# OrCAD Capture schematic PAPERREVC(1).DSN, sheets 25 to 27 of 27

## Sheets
25 PAGE1 (25): size B; title: SNAP,  ZDOK CONNECTOR; block FPGA13
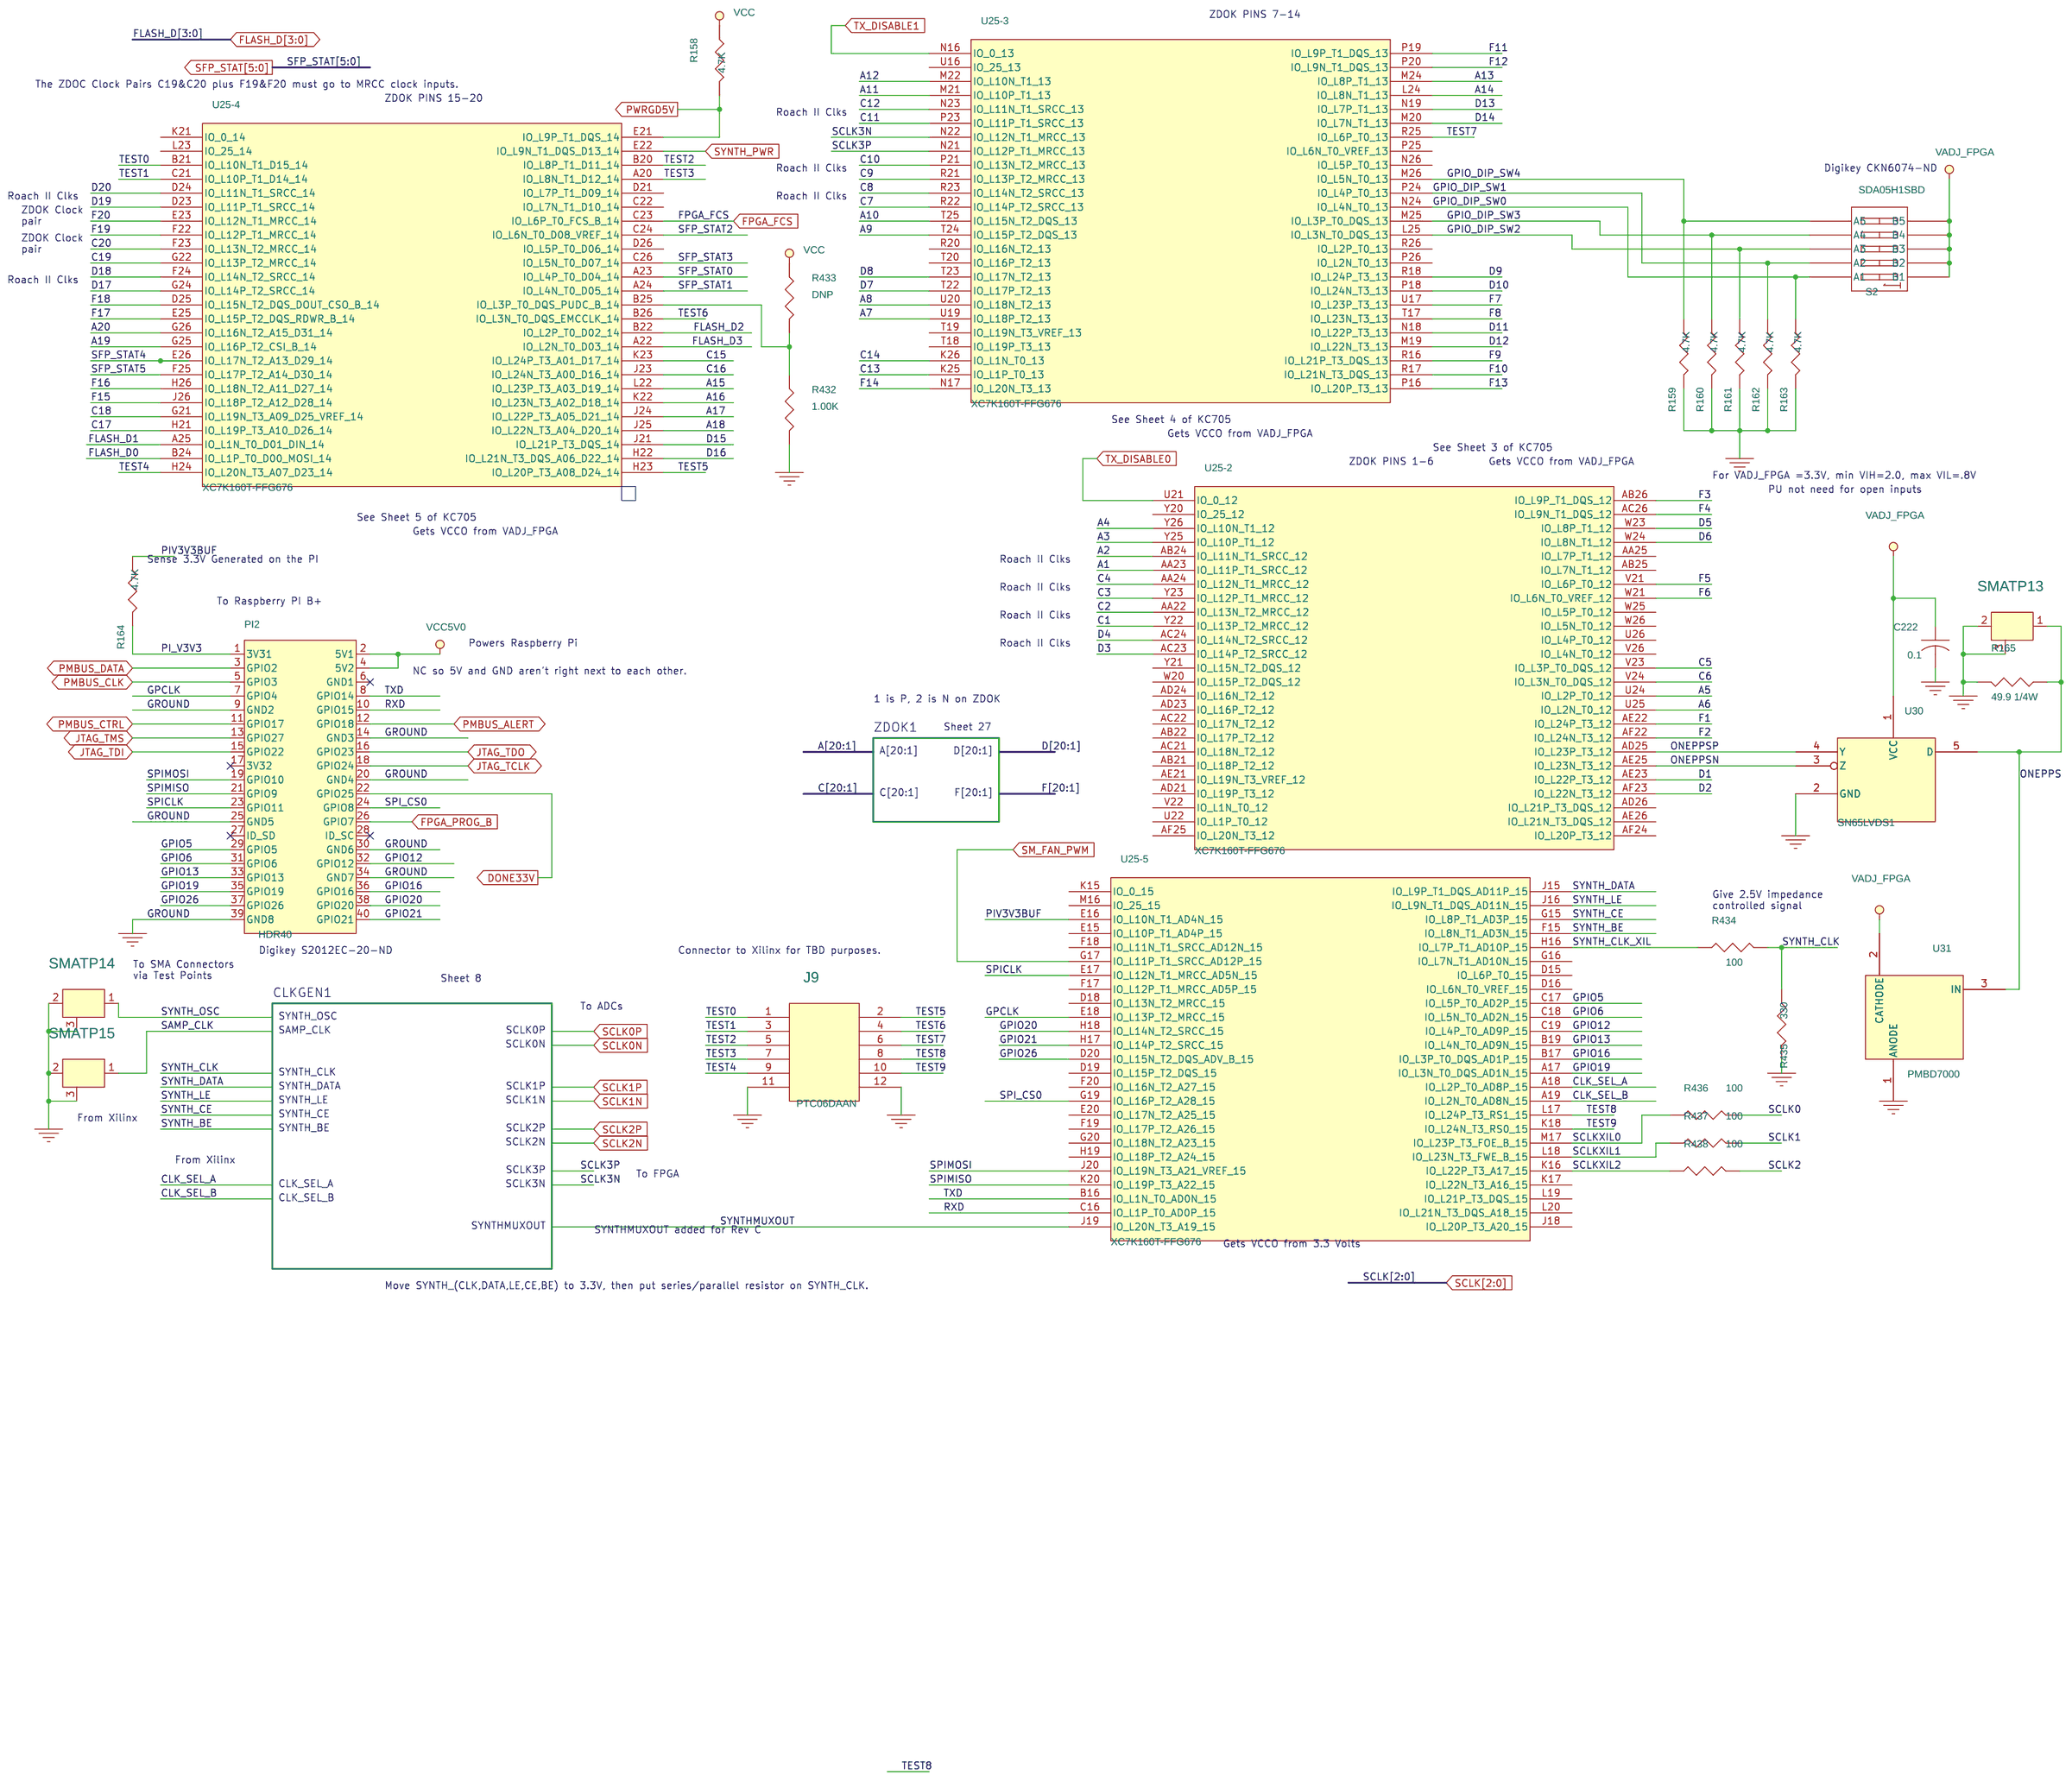
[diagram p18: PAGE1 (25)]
26 PAGE1 (26): size B; title: SNAP, Clock Generator; block FPGA13/CLKGEN1
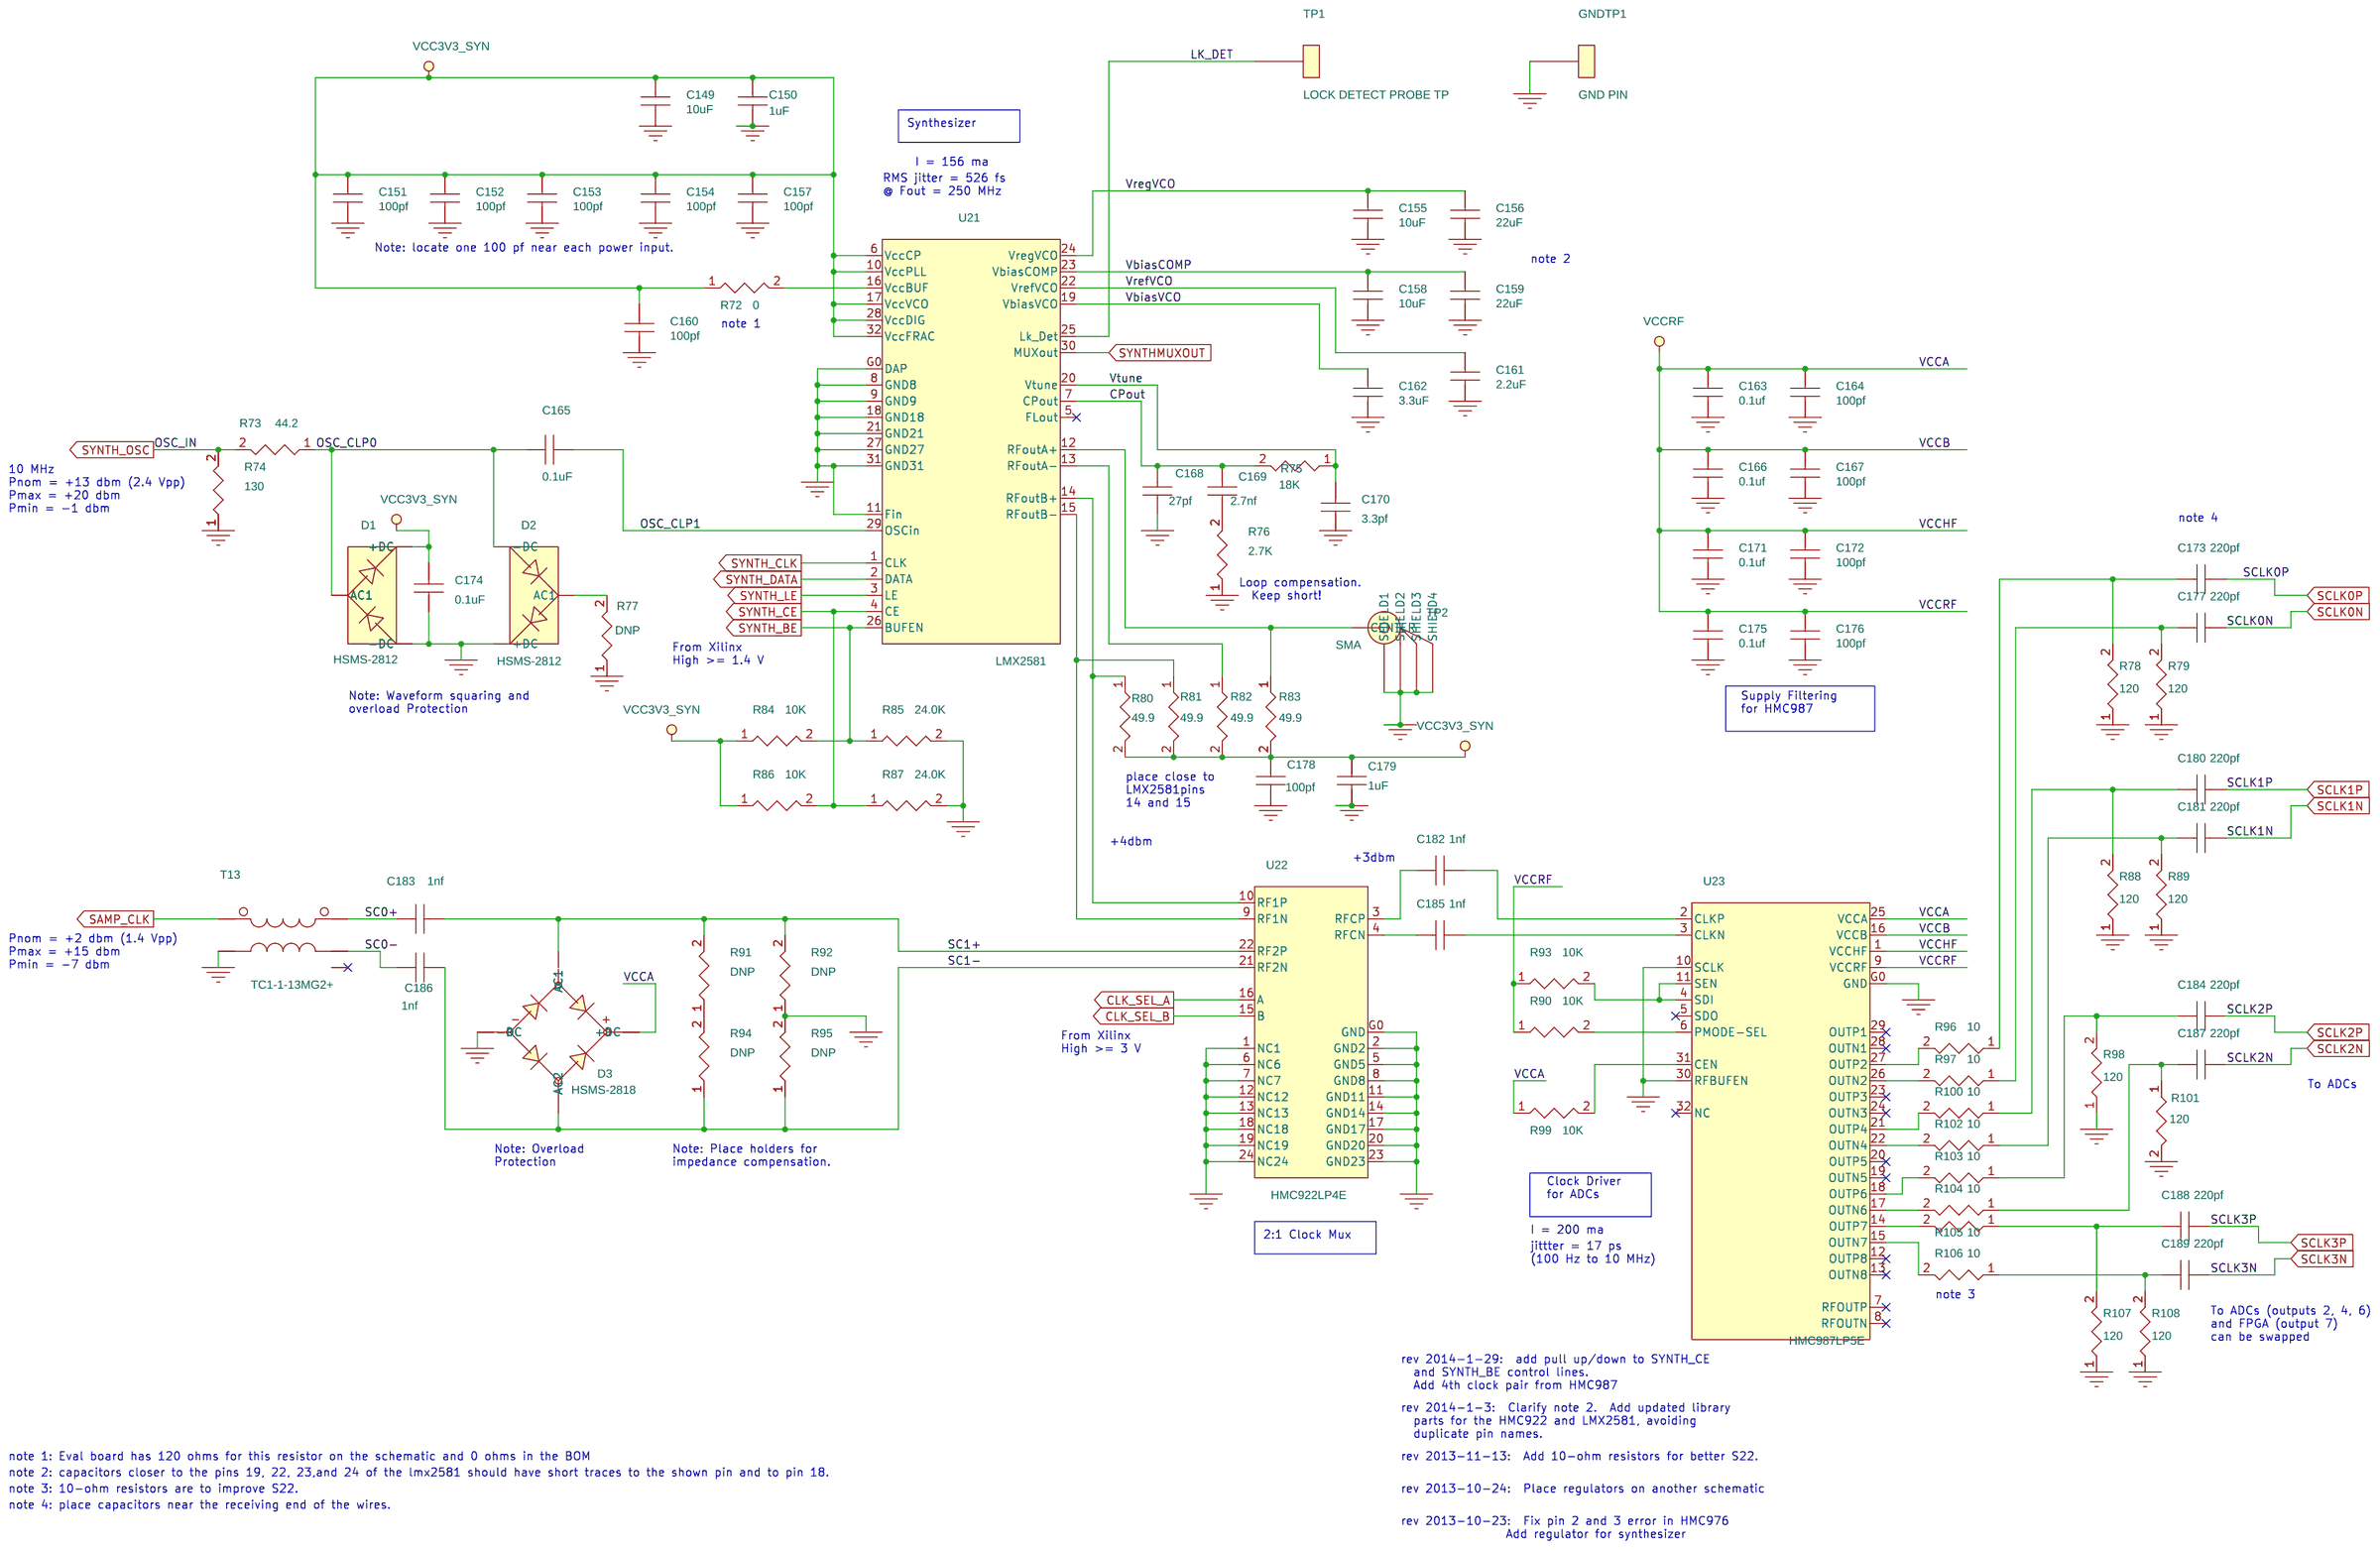
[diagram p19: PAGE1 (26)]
27 PAGE1 (27): size B; title: SNAP, ZDOK Connector; block FPGA13/ZDOK1
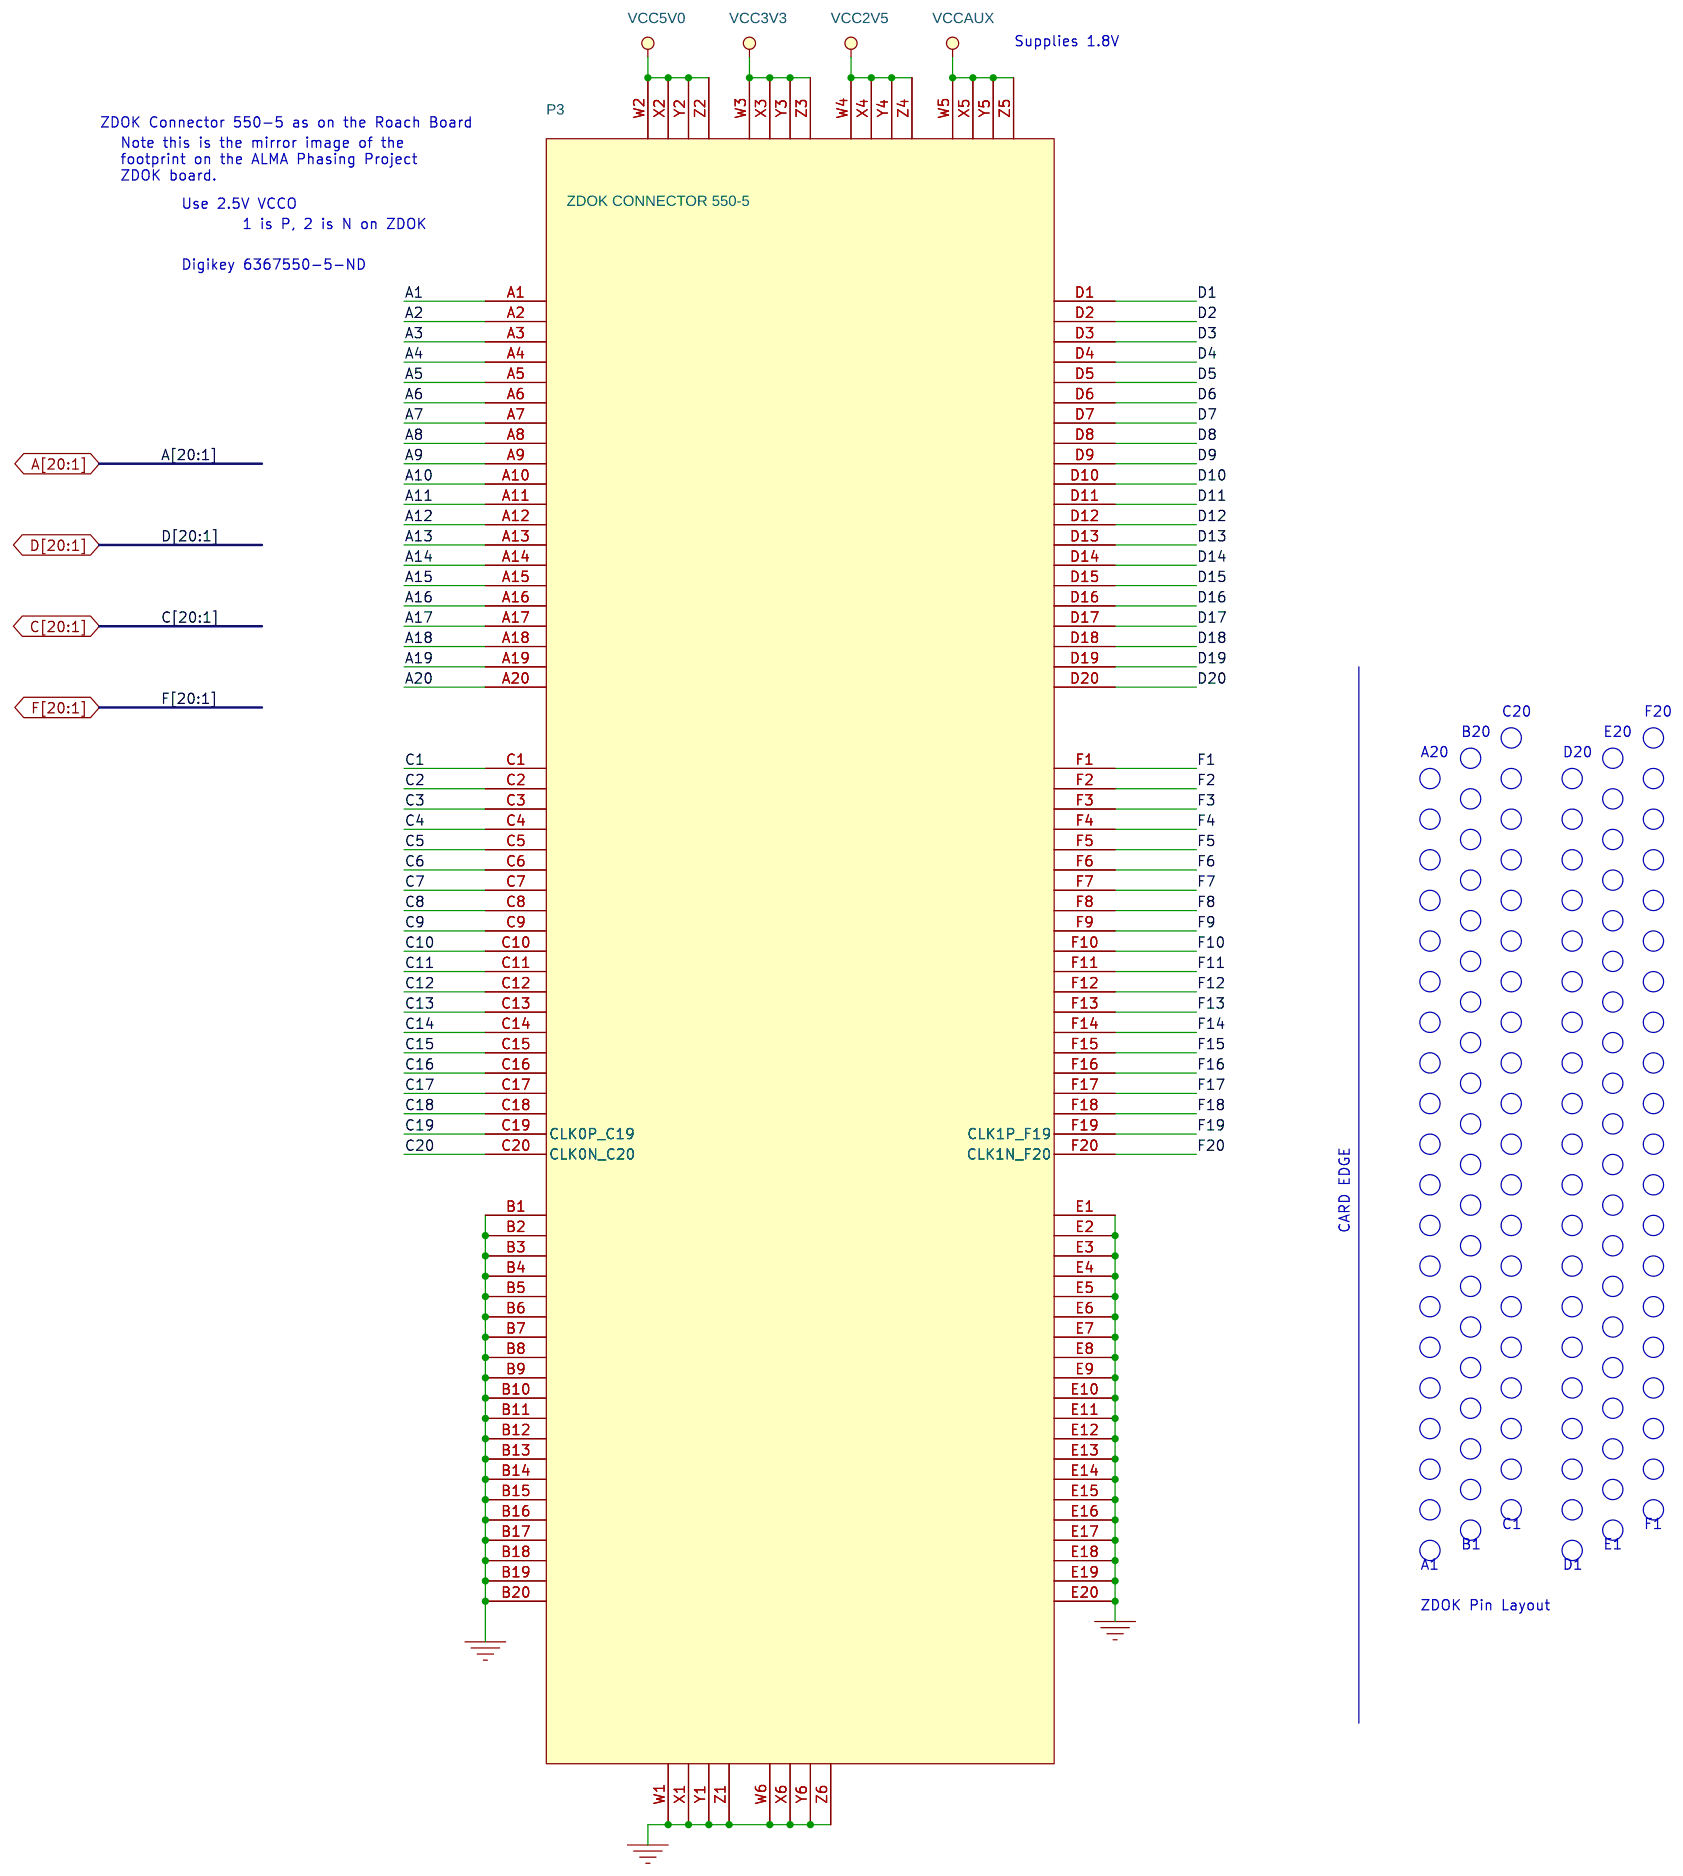
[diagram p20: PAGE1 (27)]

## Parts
sheet PAGE1 (3)
U25  XC7K160T-FFG676  [bga676c100p26x26_2700x2700x260]  (sections -1,-10,-11,-12,-13,-14,-2,-3,-4,-5,-6,-7,-8,-9)
sheet PAGE1 (25)
C222  0.1  [CAPC1005X50L]
J9  PTC06DAAN  [HDRV6X2]
PI2  HDR40  [HDRV2x20]
R158  4.7K  [RESC1005X35N]
R159  4.7K  [RESC1005X35N]
R160  4.7K  [RESC1005X35N]
R161  4.7K  [RESC1005X35N]
R162  4.7K  [RESC1005X35N]
R163  4.7K  [RESC1005X35N]
R164  4.7K  [RESC1005X35N]
R165  49.9 1/4W  [RESC3216X70N]
R432  1.00K  [RESC1005X35N]
R433  DNP  [RESC1005X35N]
R434  100  [RESC1005X35N]
R435  330  [RESC1608X50N]
R436  100  [RESC1005X35N]
R437  100  [RESC1005X35N]
R438  100  [RESC1005X35N]
S2  SDA05H1SBD  [SW_SDA05H1SBD]
SMATP13  SMATP  [SMA_END_LAUNCH]
SMATP14  SMATP  [SMA_END_LAUNCH]
SMATP15  SMATP  [SMA_END_LAUNCH]
U30  SN65LVDS1  [SOT95P280X145-5N]
U31  PMBD7000  [SOT95P240X110-3L16N]
sheet PAGE1 (26)
C149  10uF  [CAPC3216X180N]
C150  1uF  [CAPC1608X90N]
C151  100pf  [CAPC1005X50L]
C152  100pf  [CAPC1005X50L]
C153  100pf  [CAPC1005X50L]
C154  100pf  [CAPC1005X50L]
C155  10uF  [CAPC3216X180N]
C156  22uF  [CAPC3216X180N]
C157  100pf  [CAPC1005X50L]
C158  10uF  [CAPC3216X180N]
C159  22uF  [CAPC3216X180N]
C160  100pf  [CAPC1005X50L]
C161  2.2uF  [CAPC1608X90N]
C162  3.3uF  [CAPC2012X105N]
C163  0.1uf  [CAPC1005X50L]
C164  100pf  [CAPC1005X50L]
C165  0.1uF  [CAPC1005X50L]
C166  0.1uf  [CAPC1005X50L]
C167  100pf  [CAPC1005X50L]
C168  27pf  [CAPC1005X50L]
C169  2.7nf  [CAPC1608X90N]
C170  3.3pf  [CAPC1005X50N]
C171  0.1uf  [CAPC1005X50L]
C172  100pf  [CAPC1005X50L]
C173  220pf  [CAPC1005X50L]
C174  0.1uF  [CAPC1005X50L]
C175  0.1uf  [CAPC1005X50L]
C176  100pf  [CAPC1005X50L]
C177  220pf  [CAPC1005X50L]
C178  100pf  [CAPC1005X50L]
C179  1uF  [CAPC1608X90N]
C180  220pf  [CAPC1005X50L]
C181  220pf  [CAPC1005X50L]
C182  1nf  [CAPC1005X50L]
C183  1nf  [CAPC1005X50L]
C184  220pf  [CAPC1005X50L]
C185  1nf  [CAPC1005X50L]
C186  1nf  [CAPC1005X50L]
C187  220pf  [CAPC1005X50L]
C188  220pf  [CAPC1005X50L]
C189  220pf  [CAPC1005X50L]
D1  HSMS-2812  [SOT95P240X110-3L16N]
D2  HSMS-2812  [SOT95P240X110-3L16N]
D3  HSMS-2818  [SOT192P237X112-4L20N]
GNDTP1  GND PIN  [TP107]
R72  0  [RESC1005X35N]
R73  44.2  [RESC1005X35N]
R74  130  [RESC3216X70N]
R75  18K  [RESC1005X35N]
R76  2.7K  [RESC1005X35N]
R77  DNP  [RESC1005X35N]
R78  120  [RESC1608X50N]
R79  120  [RESC1608X50N]
R80  49.9  [RESC1005X35N]
R81  49.9  [RESC1005X35N]
R82  49.9  [RESC1005X35N]
R83  49.9  [RESC1005X35N]
R84  10K  [RESC1005X35N]
R85  24.0K  [RESC1005X35N]
R86  10K  [RESC1005X35N]
R87  24.0K  [RESC1005X35N]
R88  120  [RESC1608X50N]
R89  120  [RESC1608X50N]
R90  10K  [RESC1005X35N]
R91  DNP  [RESC1005X35N]
R92  DNP  [RESC1005X35N]
R93  10K  [RESC1005X35N]
R94  DNP  [RESC1005X35N]
R95  DNP  [RESC1005X35N]
R96  10  [RESC1005X35N]
R97  10  [RESC1005X35N]
R98  120  [RESC1608X50N]
R99  10K  [RESC1005X35N]
R100  10  [RESC1005X35N]
R101  120  [RESC1608X50N]
R102  10  [RESC1005X35N]
R103  10  [RESC1005X35N]
R104  10  [RESC1005X35N]
R105  10  [RESC1005X35N]
R106  10  [RESC1005X35N]
R107  120  [RESC1608X50N]
R108  120  [RESC1608X50N]
T13  TC1-1-13MG2+  [XFMR_TC1-1-13MG2]
TP1  LOCK DETECT PROBE TP  [TP107]
TP2  SMA  [EMERSON_RFCONN_SMA-V]
U21  LMX2581  [QFN50P500X500X100-33T320X320L]
U22  HMC922LP4E  [QFN50P400X400X100-25T280X280L]
U23  HMC987LP5E  [QFN50P500X500X100-33T380X380L]
sheet PAGE1 (27)
P3  ZDOK CONNECTOR 550-5  [TE_CONN_6367550-5]

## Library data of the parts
U25 = XC7K160T-FFG676
C222 = CAP_0
J9 = HEADER_6x2_SM_16: COMPHEIGHT: 0.000; DECOUPLER: NO; MEMORY: NO
PI2 = CON26A_2
R158-R165 R434-R438 = RESISTOR_0: COMPHEIGHT: 0.000; DECOUPLER: NO; MEMORY: NO; PRECISION: 5%
R432 R433 = RESISTOR_0: COMPHEIGHT: 0.000; DECOUPLER: NO; MEMORY: NO; POWER: 1/10W; PRECISION: 1%
S2 = SW_DIP-5
SMATP13-SMATP15 = HEADER_6x2_SM_25: COMPHEIGHT: 0.000; DECOUPLER: NO; MEMORY: NO
U30 = 74AHCT541_3
U31 = 74AHCT541_5
C149 C155 C158 = CAP_NP: Size: 0603; Temp. Coef.: NPO(COG); Tolerance: 10%; Voltage Rating: 10 V
C150 C179 = CAP_NP: Size: 0603; Temp. Coef.: X5R; Tolerance: 10%; Voltage Rating: 10V
C151-C154 C157 C160 C164 C167 C172 C176 C178 = CAP_NP: Size: 0402; Temp. Coef.: NPO(COG); Tolerance: 5%; Voltage Rating: 50 V
C156 C159 = CAP_NP: Size: 1206; Temp. Coef.: X5R; Tolerance: 20%; Voltage Rating: 10 V
C161 = CAP_NP: Size: 0603; Temp. Coef.: X7R; Tolerance: 15%; Voltage Rating: 10 V
C162 = CAP_NP: Size: 0805; Temp. Coef.: X5R; Tolerance: 10%; Voltage Rating: 10 V
C163 C165 C166 C171 C174 C175 = CAP_NP: Size: 0402; Temp. Coef.: X7R; Tolerance: 10 %; Voltage Rating: 16 V
C168 = CAP_NP: Digikey PN: 490-6223-1-ND; ESR: NA; Size: 0402; Temp. Coef.: NPO (COG); Tolerance: 1%; Voltage Rating: 50 V
C169 = CAP_NP: Digikey PN: 490-6383-1-ND; ESR: NA; Size: 0603; Temp. Coef.: NPO (COG); Tolerance: 2%; Voltage Rating: 50 V
C170 = CAP_NP: Digikey PN: 490-6238-2-ND; ESR: NA; Size: 0402; Temp. Coef.: NPO (COG); Tolerance: 0.1 pf; Voltage Rating: 50 V
C173 C177 C180-C182 C184 C185 C187-C189 = CAP_NP: ESR: NA; Size: 0402; Temp. Coef.: NPO (COG); Tolerance: 5%; Voltage Rating: 50 V
C183 C186 = CAP_NP: Manuf/PN: Kemet C0402C221J5GACTU; Size: 0402; Temp. Coef.: NPO(COG); Tolerance: 5%; Voltage Rating: 50 V
D1 D2 = HSMS-2812
D3 = HSMS-2818
GNDTP1 TP1 = TEST_POINT
R72 = RESISTOR_SM_1: Power Rating: 0.1 W; Size: 0603; Tolerance: 5%
R73 R77 = RESISTOR_SM_1: Power Rating: 1/16 W; Size: 0603; Temp. Coef.: 100 ppm; Tolerance: 1%
R74 = RESISTOR_SM_1: Power Rating: 1/4 W; Size: 0805; Temp. Coef.: 100 ppm; Tolerance: 1%
R75 R76 = RESISTOR_SM_1: Power Rating: 1/16 W; Size: 0402; Tolerance: 1%
R78 R79 R88 R89 R96-R98 R100-R108 = RESISTOR_SM_1: Power Rating: 1/10 W; Size: 0603; Temp. Coef.: +/- 100 PPM; Tolerance: 1%
R80-R83 = RESISTOR_SM_1: Manufacturer: Vishay Dale; Manufacturer P/N: CRCW060349R9FKEAHP; Power Rating: 1/10 W; Size: 0402; Temp. Coef.: 100 ppm; Tolerance: 1%
R84-R87 R90-R95 R99 = RESISTOR_SM_1: Power Rating: 1/16 W; Size: 0402; Tolerance: 5%
T13 = TC1-1-13M
TP2 = BNC_0
U21 = LMX2581
U22 = HMC922LP4E
U23 = HMC987LP5E
P3 = CONN_RECT_20x2_1

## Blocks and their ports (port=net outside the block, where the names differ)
FPGA13/ZDOK1 = schematic ZDOK, on sheet PAGE1: A[20:1], D[20:1], C[20:1], F[20:1]
FPGA13/CLKGEN1 = schematic CLKGEN, on sheet PAGE1: SYNTH_CLK=FPGA13/SYNTH_CLK, SYNTH_DATA=FPGA13/SYNTH_DATA, SYNTH_LE=FPGA13/SYNTH_LE, SYNTH_CE=FPGA13/SYNTH_CE, SYNTH_BE=FPGA13/SYNTH_BE, SAMP_CLK=FPGA13/SAMP_CLK, CLK_SEL_A=FPGA13/CLK_SEL_A, CLK_SEL_B=FPGA13/CLK_SEL_B, SYNTH_OSC=FPGA13/SYNTH_OSC, SCLK2P=SCLKP2, SCLK2N=SCLKN2, SCLK1P=SCLKP1, SCLK1N=SCLKN1, SCLK0P=SCLKP0, SCLK0N=SCLKN0, SCLK3N=FPGA13/SCLK3N, SCLK3P=FPGA13/SCLK3P, SYNTHMUXOUT=FPGA13/SYNTHMUXOUT

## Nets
GND: C149.2 C150.2 C151.2 C152.2 C153.2 C154.2 C155.2 C156.2 C157.2 C158.2 C159.2 C160.2 C161.2 C162.2 C163.2 C164.2 C166.2 C167.2 C168.1 C170.1 C171.2 C172.2 C174.1 C175.2 C176.2 C178.2 C179.2 C222.2 D1.1(-DC) D2.2(+DC) D3.2(-DC) GNDTP1.1 J9.11 J9.12 P3.B1 P3.B2 P3.B3 P3.B4 P3.B5 P3.B6 P3.B7 P3.B8 P3.B9 P3.B10 P3.B11 P3.B12 P3.B13 P3.B14 P3.B15 P3.B16 P3.B17 P3.B18 P3.B19 P3.B20 P3.E1 P3.E2 P3.E3 P3.E4 P3.E5 P3.E6 P3.E7 P3.E8 P3.E9 P3.E10 P3.E11 P3.E12 P3.E13 P3.E14 P3.E15 P3.E16 P3.E17 P3.E18 P3.E19 P3.E20 P3.W1 P3.W6 P3.X1 P3.X6 P3.Y1 P3.Y6 P3.Z1 P3.Z6 PI2.9(GND2) PI2.14(GND3) PI2.20(GND4) PI2.25(GND5) PI2.30(GND6) PI2.34(GND7) PI2.39(GND8) R74.1 R76.1 R77.1 R78.1 R79.1 R85.2 R87.2 R88.1 R89.1 R92.1 R95.2 R98.1 R101.2 R107.1 R108.1 R159.2 R160.2 R161.2 R162.2 R163.2 R165.2 R432.2 R435.2 SMATP13.2 SMATP13.3 SMATP14.2 SMATP14.3 SMATP15.2 SMATP15.3 T13.4 TP2.2(SHIELD1) TP2.3(SHIELD2) TP2.4(SHIELD3) TP2.5(SHIELD4) U21.8(GND8) U21.9(GND9) U21.11(Fin) U21.18(GND18) U21.21(GND21) U21.27(GND27) U21.31(GND31) U21.G0(DAP) U22.1(NC1) U22.2(GND2) U22.5(GND5) U22.6(NC6) U22.7(NC7) U22.8(GND8) U22.11(GND11) U22.12(NC12) U22.13(NC13) U22.14(GND14) U22.17(GND17) U22.18(NC18) U22.19(NC19) U22.20(GND20) U22.23(GND23) U22.24(NC24) U22.G0(GND) U23.10(SCLK) U23.30(RFBUFEN) U23.G0(GND) U30.2(GND) U31.1(ANODE) ; also on sheet 2 3 4 5 6 8 9 10 11 12 13 14 15 16 17 18 19 20 21 22 23 24
VCC3V3: P3.W3 P3.X3 P3.Y3 P3.Z3 ; also on sheet 2 9 11 12 13 14 15 22
VCC3V3_DRV: C163.1 C164.1 C166.1 C167.1 C171.1 C172.1 C175.1 C176.1 D3.3(+DC) R90.1 R93.1 R99.1 U23.1(VCCHF) U23.9(VCCRF) U23.16(VCCB) U23.25(VCCA) ; also on sheet 23
VCC3V3_SYN: C149.1 C150.1 C151.1 C152.1 C153.1 C154.1 C157.1 C160.1 C174.2 C178.1 C179.1 D1.2(+DC) R72.1 R80.2 R81.2 R82.2 R83.2 R84.1 R86.1 U21.6(VccCP) U21.10(VccPLL) U21.17(VccVCO) U21.28(VccDIG) U21.32(VccFRAC) ; also on sheet 23
VCC5V0: P3.W2 P3.X2 P3.Y2 P3.Z2 PI2.2(5V1) PI2.4(5V2) ; also on sheet 8 14 23
VCCAUX: P3.W5 P3.X5 P3.Y5 P3.Z5 ; also on sheet 9 15 22
FLASH_D0: U25.B24(IO_L1P_T0_D00_MOSI_14) ; also on sheet 24
FLASH_D1: U25.A25(IO_L1N_T0_D01_DIN_14) ; also on sheet 24
FLASH_D2: U25.B22(IO_L2P_T0_D02_14) ; also on sheet 24
FLASH_D3: U25.A22(IO_L2N_T0_D03_14) ; also on sheet 24
FPGA13/A1: P3.A1 U25.AA23(IO_L11P_T1_SRCC_12)
FPGA13/A2: P3.A2 U25.AB24(IO_L11N_T1_SRCC_12)
FPGA13/A3: P3.A3 U25.Y25(IO_L10P_T1_12)
FPGA13/A4: P3.A4 U25.Y26(IO_L10N_T1_12)
FPGA13/A5: P3.A5 U25.U24(IO_L2P_T0_12)
FPGA13/A6: P3.A6 U25.U25(IO_L2N_T0_12)
FPGA13/A7: P3.A7 U25.U19(IO_L18P_T2_13)
FPGA13/A8: P3.A8 U25.U20(IO_L18N_T2_13)
FPGA13/A9: P3.A9 U25.T24(IO_L15P_T2_DQS_13)
FPGA13/A10: P3.A10 U25.T25(IO_L15N_T2_DQS_13)
FPGA13/A11: P3.A11 U25.M21(IO_L10P_T1_13)
FPGA13/A12: P3.A12 U25.M22(IO_L10N_T1_13)
FPGA13/A13: P3.A13 U25.M24(IO_L8P_T1_13)
FPGA13/A14: P3.A14 U25.L24(IO_L8N_T1_13)
FPGA13/A15: P3.A15 U25.L22(IO_L23P_T3_A03_D19_14)
FPGA13/A16: P3.A16 U25.K22(IO_L23N_T3_A02_D18_14)
FPGA13/A17: P3.A17 U25.J24(IO_L22P_T3_A05_D21_14)
FPGA13/A18: P3.A18 U25.J25(IO_L22N_T3_A04_D20_14)
FPGA13/A19: P3.A19 U25.G25(IO_L16P_T2_CSI_B_14)
FPGA13/A20: P3.A20 U25.G26(IO_L16N_T2_A15_D31_14)
FPGA13/C1: P3.C1 U25.Y22(IO_L13P_T2_MRCC_12)
FPGA13/C2: P3.C2 U25.AA22(IO_L13N_T2_MRCC_12)
FPGA13/C3: P3.C3 U25.Y23(IO_L12P_T1_MRCC_12)
FPGA13/C4: P3.C4 U25.AA24(IO_L12N_T1_MRCC_12)
FPGA13/C5: P3.C5 U25.V23(IO_L3P_T0_DQS_12)
FPGA13/C6: P3.C6 U25.V24(IO_L3N_T0_DQS_12)
FPGA13/C7: P3.C7 U25.R22(IO_L14P_T2_SRCC_13)
FPGA13/C8: P3.C8 U25.R23(IO_L14N_T2_SRCC_13)
FPGA13/C9: P3.C9 U25.R21(IO_L13P_T2_MRCC_13)
FPGA13/C10: P3.C10 U25.P21(IO_L13N_T2_MRCC_13)
FPGA13/C11: P3.C11 U25.P23(IO_L11P_T1_SRCC_13)
FPGA13/C12: P3.C12 U25.N23(IO_L11N_T1_SRCC_13)
FPGA13/C13: P3.C13 U25.K25(IO_L1P_T0_13)
FPGA13/C14: P3.C14 U25.K26(IO_L1N_T0_13)
FPGA13/C15: P3.C15 U25.K23(IO_L24P_T3_A01_D17_14)
FPGA13/C16: P3.C16 U25.J23(IO_L24N_T3_A00_D16_14)
FPGA13/C17: P3.C17 U25.H21(IO_L19P_T3_A10_D26_14)
FPGA13/C18: P3.C18 U25.G21(IO_L19N_T3_A09_D25_VREF_14)
FPGA13/C19: P3.C19(CLK0P) U25.G22(IO_L13P_T2_MRCC_14)
FPGA13/C20: P3.C20(CLK0N) U25.F23(IO_L13N_T2_MRCC_14)
FPGA13/CLK_SEL_A: U22.16(A) U25.A18(IO_L2P_T0_AD8P_15)
FPGA13/CLK_SEL_B: U22.15(B) U25.A19(IO_L2N_T0_AD8N_15)
FPGA13/CLKGEN1/CPout: C168.2 C169.2 R75.2 U21.7(CPout)
FPGA13/CLKGEN1/LK_DET: TP1.1 U21.25(Lk_Det)
FPGA13/CLKGEN1/OSC_CLP0: C165.1 D1.3(AC1) D2.1(-DC) R73.1
FPGA13/CLKGEN1/OSC_CLP1: C165.2 U21.29(OSCin)
FPGA13/CLKGEN1/SC0+: C183.1 T13.1
FPGA13/CLKGEN1/SC0-: C186.1 T13.3
FPGA13/CLKGEN1/SC1+: C183.2 D3.1(AC1) R91.2 R92.2 U22.22(RF2P)
FPGA13/CLKGEN1/SC1-: C186.2 D3.4(AC2) R94.1 R95.1 U22.21(RF2N)
FPGA13/CLKGEN1/VbiasCOMP: C158.1 C159.1 U21.23(VbiasCOMP)
FPGA13/CLKGEN1/VbiasVCO: C162.1 U21.19(VbiasVCO)
FPGA13/CLKGEN1/VrefVCO: C161.1 U21.22(VrefVCO)
FPGA13/CLKGEN1/VregVCO: C155.1 C156.1 U21.24(VregVCO)
FPGA13/CLKGEN1/Vtune: C170.2 R75.1 U21.20(Vtune)
FPGA13/D1: P3.D1 U25.AE23(IO_L22P_T3_12)
FPGA13/D2: P3.D2 U25.AF23(IO_L22N_T3_12)
FPGA13/D3: P3.D3 U25.AC23(IO_L14P_T2_SRCC_12)
FPGA13/D4: P3.D4 U25.AC24(IO_L14N_T2_SRCC_12)
FPGA13/D5: P3.D5 U25.W23(IO_L8P_T1_12)
FPGA13/D6: P3.D6 U25.W24(IO_L8N_T1_12)
FPGA13/D7: P3.D7 U25.T22(IO_L17P_T2_13)
FPGA13/D8: P3.D8 U25.T23(IO_L17N_T2_13)
FPGA13/D9: P3.D9 U25.R18(IO_L24P_T3_13)
FPGA13/D10: P3.D10 U25.P18(IO_L24N_T3_13)
FPGA13/D11: P3.D11 U25.N18(IO_L22P_T3_13)
FPGA13/D12: P3.D12 U25.M19(IO_L22N_T3_13)
FPGA13/D13: P3.D13 U25.N19(IO_L7P_T1_13)
FPGA13/D14: P3.D14 U25.M20(IO_L7N_T1_13)
FPGA13/D15: P3.D15 U25.J21(IO_L21P_T3_DQS_14)
FPGA13/D16: P3.D16 U25.H22(IO_L21N_T3_DQS_A06_D22_14)
FPGA13/D17: P3.D17 U25.G24(IO_L14P_T2_SRCC_14)
FPGA13/D18: P3.D18 U25.F24(IO_L14N_T2_SRCC_14)
FPGA13/D19: P3.D19 U25.D23(IO_L11P_T1_SRCC_14)
FPGA13/D20: P3.D20 U25.D24(IO_L11N_T1_SRCC_14)
FPGA13/F1: P3.F1 U25.AE22(IO_L24P_T3_12)
FPGA13/F2: P3.F2 U25.AF22(IO_L24N_T3_12)
FPGA13/F3: P3.F3 U25.AB26(IO_L9P_T1_DQS_12)
FPGA13/F4: P3.F4 U25.AC26(IO_L9N_T1_DQS_12)
FPGA13/F5: P3.F5 U25.V21(IO_L6P_T0_12)
FPGA13/F6: P3.F6 U25.W21(IO_L6N_T0_VREF_12)
FPGA13/F7: P3.F7 U25.U17(IO_L23P_T3_13)
FPGA13/F8: P3.F8 U25.T17(IO_L23N_T3_13)
FPGA13/F9: P3.F9 U25.R16(IO_L21P_T3_DQS_13)
FPGA13/F10: P3.F10 U25.R17(IO_L21N_T3_DQS_13)
FPGA13/F11: P3.F11 U25.P19(IO_L9P_T1_DQS_13)
FPGA13/F12: P3.F12 U25.P20(IO_L9N_T1_DQS_13)
FPGA13/F13: P3.F13 U25.P16(IO_L20P_T3_13)
FPGA13/F14: P3.F14 U25.N17(IO_L20N_T3_13)
FPGA13/F15: P3.F15 U25.J26(IO_L18P_T2_A12_D28_14)
FPGA13/F16: P3.F16 U25.H26(IO_L18N_T2_A11_D27_14)
FPGA13/F17: P3.F17 U25.E25(IO_L15P_T2_DQS_RDWR_B_14)
FPGA13/F18: P3.F18 U25.D25(IO_L15N_T2_DQS_DOUT_CSO_B_14)
FPGA13/F19: P3.F19(CLK1P) U25.F22(IO_L12P_T1_MRCC_14)
FPGA13/F20: P3.F20(CLK1N) U25.E23(IO_L12N_T1_MRCC_14)
FPGA13/GPCLK: PI2.7(GPIO4) U25.E18(IO_L13P_T2_MRCC_15)
FPGA13/GPIO5: PI2.29(GPIO5) U25.C17(IO_L5P_T0_AD2P_15)
FPGA13/GPIO6: PI2.31(GPIO6) U25.C18(IO_L5N_T0_AD2N_15)
FPGA13/GPIO12: PI2.32(GPIO12) U25.C19(IO_L4P_T0_AD9P_15)
FPGA13/GPIO13: PI2.33(GPIO13) U25.B19(IO_L4N_T0_AD9N_15)
FPGA13/GPIO16: PI2.36(GPIO16) U25.B17(IO_L3P_T0_DQS_AD1P_15)
FPGA13/GPIO19: PI2.35(GPIO19) U25.A17(IO_L3N_T0_DQS_AD1N_15)
FPGA13/GPIO20: PI2.38(GPIO20) U25.H18(IO_L14N_T2_SRCC_15)
FPGA13/GPIO21: PI2.40(GPIO21) U25.H17(IO_L14P_T2_SRCC_15)
FPGA13/GPIO26: PI2.37(GPIO26) U25.D20(IO_L15N_T2_DQS_ADV_B_15)
FPGA13/GPIO_DIP_SW0: R163.1 S2.1(A1) U25.N24(IO_L4N_T0_13)
FPGA13/GPIO_DIP_SW1: R162.1 S2.2(A2) U25.P24(IO_L4P_T0_13)
FPGA13/GPIO_DIP_SW2: R161.1 S2.3(A3) U25.L25(IO_L3N_T0_DQS_13)
FPGA13/GPIO_DIP_SW3: R160.1 S2.4(A4) U25.M25(IO_L3P_T0_DQS_13)
FPGA13/GPIO_DIP_SW4: R159.1 S2.5(A5) U25.M26(IO_L5N_T0_13)
FPGA13/ONEPPS: R165.1 SMATP13.1 U30.5(D) U31.3(IN)
FPGA13/ONEPPSN: U25.AE25(IO_L23N_T3_12) U30.3(Z)
FPGA13/ONEPPSP: U25.AD25(IO_L23P_T3_12) U30.4(Y)
FPGA13/PI_V3V3: PI2.1(3V31) R164.2
FPGA13/PIV3V3BUF: R164.1 U25.E16(IO_L10N_T1_AD4N_15)
FPGA13/RXD: PI2.10(GPIO15) U25.C16(IO_L1P_T0_AD0P_15)
FPGA13/SAMP_CLK: SMATP15.1 T13.6
FPGA13/SCLK3N: C189.2 U25.N22(IO_L12N_T1_MRCC_13)
FPGA13/SCLK3P: C188.2 U25.N21(IO_L12P_T1_MRCC_13)
FPGA13/SCLKXIL0: R436.1 U25.M17(IO_L23P_T3_FOE_B_15)
FPGA13/SCLKXIL1: R437.1 U25.L18(IO_L23N_T3_FWE_B_15)
FPGA13/SCLKXIL2: R438.1 U25.K16(IO_L22P_T3_A17_15)
FPGA13/SPI_CS0: PI2.24(GPIO8) U25.G19(IO_L16P_T2_A28_15)
FPGA13/SPICLK: PI2.23(GPIO11) U25.E17(IO_L12N_T1_MRCC_AD5N_15)
FPGA13/SPIMISO: PI2.21(GPIO9) U25.K20(IO_L19P_T3_A22_15)
FPGA13/SPIMOSI: PI2.19(GPIO10) U25.J20(IO_L19N_T3_A21_VREF_15)
FPGA13/SYNTH_BE: R84.2 R85.1 U21.26(BUFEN) U25.F15(IO_L8N_T1_AD3N_15)
FPGA13/SYNTH_CE: R86.2 R87.1 U21.4(CE) U25.G15(IO_L8P_T1_AD3P_15)
FPGA13/SYNTH_CLK: R434.2 R435.1 U21.1(CLK)
FPGA13/SYNTH_CLK_XIL: R434.1 U25.H16(IO_L7P_T1_AD10P_15)
FPGA13/SYNTH_DATA: U21.2(DATA) U25.J15(IO_L9P_T1_DQS_AD11P_15)
FPGA13/SYNTH_LE: U21.3(LE) U25.J16(IO_L9N_T1_DQS_AD11N_15)
FPGA13/SYNTH_OSC: R73.2 R74.2 SMATP14.1
FPGA13/SYNTHMUXOUT: U21.30(MUXout) U25.J19(IO_L20N_T3_A19_15)
FPGA13/TEST0: J9.1 U25.B21(IO_L10N_T1_D15_14)
FPGA13/TEST1: J9.3 U25.C21(IO_L10P_T1_D14_14)
FPGA13/TEST2: J9.5 U25.B20(IO_L8P_T1_D11_14)
FPGA13/TEST3: J9.7 U25.A20(IO_L8N_T1_D12_14)
FPGA13/TEST4: J9.9 U25.H24(IO_L20N_T3_A07_D23_14)
FPGA13/TEST5: J9.2 U25.H23(IO_L20P_T3_A08_D24_14)
FPGA13/TEST6: J9.4 U25.B26(IO_L3N_T0_DQS_EMCCLK_14)
FPGA13/TEST7: J9.6 U25.R25(IO_L6P_T0_13)
FPGA13/TEST8: J9.8 U25.L17(IO_L24P_T3_RS1_15)
FPGA13/TEST9: J9.10 U25.K18(IO_L24N_T3_RS0_15)
FPGA13/TXD: PI2.8(GPIO14) U25.B16(IO_L1N_T0_AD0N_15)
FPGA_FCS: U25.C23(IO_L6P_T0_FCS_B_14) ; also on sheet 2
SCLK0: R436.2 ; also on sheet 5
SCLK1: R437.2 ; also on sheet 6
SCLK2: R438.2 ; also on sheet 4
SCLKN0: C177.2 ; also on sheet 5
SCLKN1: C181.2 ; also on sheet 6
SCLKN2: C187.2 ; also on sheet 4
SCLKP0: C173.2 ; also on sheet 5
SCLKP1: C180.2 ; also on sheet 6
SCLKP2: C184.2 ; also on sheet 4
SFP_STAT0: U25.A23(IO_L4P_T0_D04_14) ; also on sheet 11
SFP_STAT1: U25.A24(IO_L4N_T0_D05_14) ; also on sheet 11
SFP_STAT2: U25.C24(IO_L6N_T0_D08_VREF_14) ; also on sheet 11
SFP_STAT3: U25.C26(IO_L5N_T0_D07_14) ; also on sheet 13
SFP_STAT4: U25.E26(IO_L17N_T2_A13_D29_14) ; also on sheet 13
SFP_STAT5: U25.F25(IO_L17P_T2_A14_D30_14) ; also on sheet 13
VADJ: C222.1 P3.W4 P3.X4 P3.Y4 P3.Z4 R158.1 R433.1 S2.6(B5) S2.7(B4) S2.8(B3) S2.9(B2) S2.10(B1) U30.1(VCC) U31.2(CATHODE) ; also on sheet 2 9 10 11 12 13 14 15 18 23 24
FPGA13/CLKGEN1/N10008159: R80.1 U21.14(RFoutB+) U22.10(RF1P)
FPGA13/CLKGEN1/N10008325: R72.2 U21.16(VccBUF)
FPGA13/CLKGEN1/N10008615: C187.1 R101.1 R104.1
FPGA13/CLKGEN1/N10008693: R103.2 U23.18(OUTP6)
FPGA13/CLKGEN1/N10008707: C184.1 R98.2 R103.1
FPGA13/CLKGEN1/N10009061: R104.2 U23.17(OUTN6)
FPGA13/CLKGEN1/N10009111: R81.1 U21.15(RFoutB-) U22.9(RF1N)
FPGA13/CLKGEN1/N10009213: R82.1 U21.13(RFoutA-)
FPGA13/CLKGEN1/N10009251: R83.1 TP2.1(CENTER) U21.12(RFoutA+)
FPGA13/CLKGEN1/N10009267: R105.2 U23.14(OUTP7)
FPGA13/CLKGEN1/N10009287: R106.2 U23.15(OUTN7)
FPGA13/CLKGEN1/N10009295: C189.1 R106.1 R108.2
FPGA13/CLKGEN1/N10009299: C188.1 R105.1 R107.2
FPGA13/CLKGEN1/N10009575: C181.1 R89.2 R102.1
FPGA13/CLKGEN1/N10009619: C180.1 R88.2 R100.1
FPGA13/CLKGEN1/N10009647: R102.2 U23.22(OUTN4)
FPGA13/CLKGEN1/N10009651: R100.2 U23.21(OUTP4)
FPGA13/CLKGEN1/N10009683: R97.2 U23.26(OUTN2)
FPGA13/CLKGEN1/N10009717: R96.2 U23.27(OUTP2)
FPGA13/CLKGEN1/N10010011: C173.1 R78.2 R96.1
FPGA13/CLKGEN1/N10010015: C177.1 R79.2 R97.1
FPGA13/CLKGEN1/N10010273: C185.2 U23.3(CLKN)
FPGA13/CLKGEN1/N10010277: C182.2 U23.2(CLKP)
FPGA13/CLKGEN1/N10010289: C182.1 U22.3(RFCP)
FPGA13/CLKGEN1/N10010301: C185.1 U22.4(RFCN)
FPGA13/CLKGEN1/N10010497: R93.2 U23.4(SDI) U23.11(SEN)
FPGA13/CLKGEN1/N10011263: R90.2 U23.6(PMODE-SEL)
FPGA13/CLKGEN1/N10011311: R99.2 U23.31(CEN)
FPGA13/CLKGEN1/N10011347: D2.3(AC1) R77.2
FPGA13/N10094052: R432.1 R433.2 U25.B25(IO_L3P_T0_DQS_PUDC_B_14)
N9912452: PI2.26(GPIO7) ; also on sheet 2 24
N9912646: U25.U21(IO_0_12) ; also on sheet 11
N9913062: U25.N16(IO_0_13) ; also on sheet 13
N9962816: U25.E22(IO_L9N_T1_DQS_D13_14) ; also on sheet 23
N9963272: R158.2 U25.E21(IO_L9P_T1_DQS_14) ; also on sheet 8
N9967310: PI2.3(GPIO2) ; also on sheet 3 15 20 21
N9967323: PI2.5(GPIO3) ; also on sheet 3 15 20 21
N9967336: PI2.12(GPIO18) ; also on sheet 3 15 20 21
N9967512: PI2.11(GPIO17) ; also on sheet 15 20 21
N9967965: PI2.13(GPIO27) ; also on sheet 2
N9967983: PI2.15(GPIO22) ; also on sheet 2
N9967995: PI2.16(GPIO23) ; also on sheet 2
N9968007: PI2.18(GPIO24) ; also on sheet 2
N9998463: U25.G17(IO_L11P_T1_SRCC_AD12P_15) ; also on sheet 15
N10001808: PI2.22(GPIO25) ; also on sheet 14
N10064978: C169.1 R76.2
N10064980: R91.1 R94.2

Not connected (* = marked no-connect by the designer): PI2 6(GND1)* 17(3V32)* 27(ID_SD)* 28(ID_SC)*; T13 2*; U21 5(FLout)*; U23 5(SDO)* 7(RFOUTP)* 8(RFOUTN)* 12(OUTP8)* 13(OUTN8)* 19(OUTN5)* 20(OUTP5)* 23(OUTP3)* 24(OUTN3)* 28(OUTN1)* 29(OUTP1)* 32(NC)*; U25 AA25(IO_L7P_T1_12) AB21(IO_L18P_T2_12) AB22(IO_L17P_T2_12) AB25(IO_L7N_T1_12) AC21(IO_L18N_T2_12) AC22(IO_L17N_T2_12) AD21(IO_L19P_T3_12) AD23(IO_L16P_T2_12) AD24(IO_L16N_T2_12) AD26(IO_L21P_T3_DQS_12) AE21(IO_L19N_T3_VREF_12) AE26(IO_L21N_T3_DQS_12) AF24(IO_L20P_T3_12) AF25(IO_L20N_T3_12) C22(IO_L7N_T1_D10_14) D15(IO_L6P_T0_15) D16(IO_L6N_T0_VREF_15) D18(IO_L13N_T2_MRCC_15) D19(IO_L15P_T2_DQS_15) D21(IO_L7P_T1_D09_14) D26(IO_L5P_T0_D06_14) E15(IO_L10P_T1_AD4P_15) E20(IO_L17N_T2_A25_15) F17(IO_L12P_T1_MRCC_AD5P_15) F18(IO_L11N_T1_SRCC_AD12N_15) F19(IO_L17P_T2_A26_15) F20(IO_L16N_T2_A27_15) G16(IO_L7N_T1_AD10N_15) G20(IO_L18N_T2_A23_15) H19(IO_L18P_T2_A24_15) J18(IO_L20P_T3_A20_15) K15(IO_0_15) K17(IO_L22N_T3_A16_15) K21(IO_0_14) L19(IO_L21P_T3_DQS_15) L20(IO_L21N_T3_DQS_A18_15) L23(IO_25_14) M16(IO_25_15) N26(IO_L5P_T0_13) P25(IO_L6N_T0_VREF_13) P26(IO_L2N_T0_13) R20(IO_L16N_T2_13) R26(IO_L2P_T0_13) T18(IO_L19P_T3_13) T19(IO_L19N_T3_VREF_13) T20(IO_L16P_T2_13) U16(IO_25_13) U22(IO_L1P_T0_12) U26(IO_L4P_T0_12) V22(IO_L1N_T0_12) V26(IO_L4N_T0_12) W20(IO_L15P_T2_DQS_12) W25(IO_L5P_T0_12) W26(IO_L5N_T0_12) Y20(IO_25_12) Y21(IO_L15N_T2_DQS_12)

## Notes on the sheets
sheet 25
- ZDOK PINS 7-14
- The ZDOC Clock Pairs C19&C20 plus F19&F20 must go to MRCC clock inputs.
- ZDOK PINS 15-20
- Roach II Clks
- Roach II Clks
- Digikey CKN6074-ND
- Roach II Clks
- Roach II Clks
- ZDOK Clock
  pair
- ZDOK Clock
  pair
- Roach II Clks
- See Sheet 4 of KC705
- Gets VCCO from VADJ_FPGA
- See Sheet 3 of KC705
- ZDOK PINS 1-6
- Gets VCCO from VADJ_FPGA
- For VADJ_FPGA =3.3V, min VIH=2.0, max VIL=.8V
- PU not need for open inputs
- See Sheet 5 of KC705
- Gets VCCO from VADJ_FPGA
- Sense 3.3V Generated on the PI
- Roach II Clks
- Roach II Clks
- To Raspberry PI B+
- Roach II Clks
- Powers Raspberry Pi
- Roach II Clks
- NC so 5V and GND aren't right next to each other.
- 1 is P, 2 is N on ZDOK
- Sheet 27
- Give 2.5V impedance
  controlled signal
- Digikey S2012EC-20-ND
- Connector to Xilinx for TBD purposes.
- To SMA Connectors
  via Test Points
- Sheet 8
- To ADCs
- From Xilinx
- From Xilinx
- To FPGA
- SYNTHMUXOUT added for Rev C
- Gets VCCO from 3.3 Volts
- Move SYNTH_(CLK,DATA,LE,CE,BE) to 3.3V, then put series/parallel resistor on SYNTH_CLK.
sheet 26
- Synthesizer
- RMS jitter = 526 fs
  @ Fout = 250 MHz
- I = 156 ma
- Note: locate one 100 pf near each power input.
- note 2
- note 1
- 10 MHz
  Pnom = +13 dbm (2.4 Vpp)
  Pmax = +20 dbm
  Pmin = -1 dbm
- note 4
- Loop compensation.
    Keep short!
- From Xilinx
  High >= 1.4 V
- Note: Waveform squaring and
  overload Protection
- Supply Filtering
  for HMC987
- place close to
  LMX2581pins
  14 and 15
- +4dbm
- +3dbm
- Pnom = +2 dbm (1.4 Vpp)
  Pmax = +15 dbm
  Pmin = -7 dbm
- From Xilinx
  High >= 3 V
- To ADCs
- Note: Overload
  Protection
- Note: Place holders for
  impedance compensation.
- Clock Driver
  for ADCs
- I = 200 ma
- 2:1 Clock Mux
- jittter = 17 ps
  (100 Hz to 10 MHz)
- note 3
- To ADCs (outputs 2, 4, 6)
  and FPGA (output 7)
  can be swapped
- rev 2014-1-29:  add pull up/down to SYNTH_CE
    and SYNTH_BE control lines.
    Add 4th clock pair from HMC987
- rev 2014-1-3:  Clarify note 2.  Add updated library
    parts for the HMC922 and LMX2581, avoiding
    duplicate pin names.
- note 1: Eval board has 120 ohms for this resistor on the schematic and 0 ohms in the BOM
- rev 2013-11-13:  Add 10-ohm resistors for better S22.
- note 2: capacitors closer to the pins 19, 22, 23,and 24 of the lmx2581 should have short traces to the shown pin and to pin 18.
- note 3: 10-ohm resistors are to improve S22.
- rev 2013-10-24:  Place regulators on another schematic
- note 4: place capacitors near the receiving end of the wires.
- rev 2013-10-23:  Fix pin 2 and 3 error in HMC976
                   Add regulator for synthesizer
sheet 27
- Supplies 1.8V
- ZDOK Connector 550-5 as on the Roach Board
- Note this is the mirror image of the
  footprint on the ALMA Phasing Project
  ZDOK board.
- Use 2.5V VCCO
- 1 is P, 2 is N on ZDOK
- Digikey 6367550-5-ND
- C20
- F20
- B20
- E20
- A20
- D20
- CARD EDGE
- C1
- F1
- A1
- B1
- D1
- E1
- ZDOK Pin Layout
